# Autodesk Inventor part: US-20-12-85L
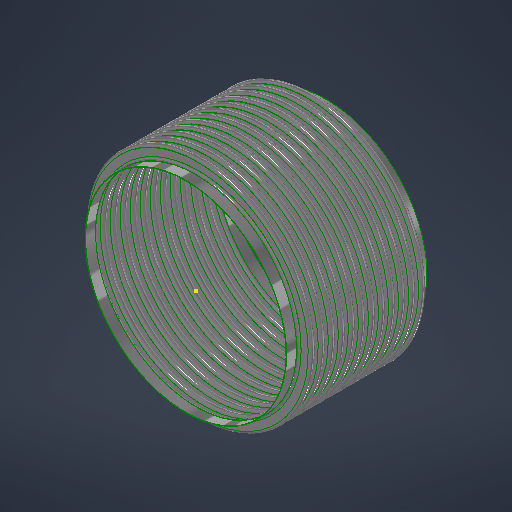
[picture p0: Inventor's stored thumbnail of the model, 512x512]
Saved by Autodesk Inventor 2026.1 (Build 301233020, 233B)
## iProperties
Category: 18 GA (0.048 THICK)
RuleStatus: InUse
Created: 2026-07
Part Number: US-20-12-85L
Project: =STOCK BELLOWS: <Stock Number><SFILL>
Material: ASTM A240-304
Description: =STOCK BELLOWS: <Stock Number>, <SID_> I.D., <SOD_> O.D., <SPLY_> PLY, <Category>, <SNET_CONS> CONS.<PITCH_><STANGENT_> TANGENT<SFILL>
Document SubType Name: Sheet Metal
Designer: LC
Stock Number: U.S-20-12-85L
Surface Area: 659.127 cm^2
Volume: 56.61 cm^3
Sheet Metal Rule: Default
Appearance: STAINLESS STEEL
NET_TUBE: 3.428
COUNTER: 1.500
PBAR: 1.214
PSET: 5.356
PLY: 2
CONS: 2
THK: 0.036
ID: 4.500
OD: 5.500
CONS_: 2
TANGENT: 0.500
PITCH: 0.375
BELLOWS_UPSET: 0.000
NET_CONS: 2
S_CONS: 0
Description_Units: 0
ID_M: 114.30 mm
OD_M: 139.70 mm
THK_M: 0.91 mm
ID_U: 4.500 in
OD_U: 5.500 in
THK_U: 0.036 in
TANGENT2: 0.500
d79: 1.000
d82: 1.000
d83: 26.000
d84: 24.000
d80: 2.571
d81: 10
SID: 2.375
SCONS_: 12
SPITCH: 0.250
SBELLOWS_UPSET: 0.000
SNET_CONS: 12
SS_CONS: 0
SCONS: 8
d174: 8
d177: 0.018
d178: 2.375
d179: 3.000
d180: 0.375
d181: 1.000
d182: 0.000
d190: 8
d191: 1
d192: 1
d193: 8
d194: 0
PART_NUMBER: U.S-20-12-85L
PRESSURE: 85
SIZE: 20.00
STANGENT_: 1.000
d214: 8
d217: 0.030
d218: 6.625
d219: 8.125
d220: 0.500
d221: 1.000
d222: 0.000
d230: 8
d231: 1
d232: 1
d233: 8
d234: 0
STANGENT: 4.000
SPLY_: 1
STHK_: 0.048
SID_: 20.000
SOD_: 22.500
SPITCH_: 1.000
STANGENT__: 1.000
SBELLOWS_UPSET_: 0.000
SDIFF_TAN: 1.000
TAN_TO_TAN: 0.750 in
d252: 2
d275: 2
d287: 0.050
d289: 0.500
d290: 0.000
d263: 2
d265: 1
d268: 2
d269: 0
d286: 2
d288: 1
d291: 2
d292: 0
SOD_NECK: 20 1/8
CFILL: .
SFILL: .
PITCH_: =, <SPITCH_> PITCH,
SREROLL: 0.750
MATTABLE: 20 GA (0.036 THICK)
MESH: ,
CSECT: 2
Author: LC
Keywords: 20 GA (0.036 THICK)
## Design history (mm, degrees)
sketch "Sketch2"
  geometry: L1 (0, -183.595)-(0, 600.956) reference; L2 (58.979, 0)-(57.15, 0); L3 (60.446, -1.467)-(66.554, -1.467); L4 (60.446, -3.296)-(66.554, -3.296); L5 (66.554, -8.058)-(60.446, -8.058); L6 (66.554, -6.229)-(60.446, -6.229); L7 (58.979, -9.525)-(57.15, -9.525); L8 (60.446, 0)-(60.446, -9.525); L9 (66.554, -4.762)-(69.85, -4.763); L10 (57.15, 0)-(57.15, -9.525); L11 (20.376, 102.841)-(20.376, 101.926); L12 (58.262, 488.877)-(58.262, 349.177); L13 (58.262, 479.352)-(58.262, 339.652); L14 (93.133, -58.817)-(93.133, -71.517); L15 (118.746, -66.401)-(118.746, -66.401); L16 (66.554, -6.229)-(66.554, -8.058); L17 (60.446, -6.229)-(60.446, -8.058); L18 (60.446, -7.144)-(66.554, -7.144); L19 (69.85, 0)-(69.85, -9.525); L20 (-66.554, -6.229)-(-66.554, -8.058); L21 (-66.554, -1.467)-(-60.446, -1.467); L22 (-66.554, -3.296)-(-60.446, -3.296); L23 (-60.446, -6.229)-(-66.554, -6.229); L24 (-66.554, -7.144)-(-60.446, -7.144); L25 (-60.446, -8.058)-(-66.554, -8.058); L26 (-60.446, -6.229)-(-60.446, -8.058); L27 (-57.15, -2.522)-(-57.15, -12.047); L28 (-60.446, -4.763)-(-57.15, -4.763); L29 (-66.554, 3.828)-(-66.554, -9.525); L30 (-68.021, 0)-(-69.85, 0); L31 (-69.85, 0)-(-69.85, -9.525); L32 (-68.021, -9.525)-(-69.85, -9.525); A1 r 1.467 centre (60.446, 0) between (58.979, 0) and (60.446, -1.467); A2 r 3.296 centre (60.446, 0) between (57.15, 0) and (60.446, -3.296); A3 r 3.296 centre (66.554, -4.762) between (66.554, -8.058) and (66.554, -1.467); A4 r 1.467 centre (66.554, -4.762) between (66.554, -6.229) and (66.554, -3.296); A5 r 1.467 centre (60.446, -9.525) between (60.446, -8.058) and (58.979, -9.525); A6 r 3.296 centre (60.446, -9.525) between (60.446, -6.229) and (57.15, -9.525); A7 r 2.381 centre (66.554, -4.762) between (66.554, -7.144) and (68.936, -4.762); A8 r 2.381 centre (60.446, -9.525) between (60.446, -7.144) and (58.064, -9.525); A9 r 1.467 centre (-66.554, -9.525) between (-66.554, -8.058) and (-68.021, -9.525); A10 r 1.467 centre (-60.446, -4.763) between (-60.446, -6.229) and (-60.446, -3.296); A11 r 2.381 centre (-60.446, -4.763) between (-60.446, -7.144) and (-58.064, -4.763); A12 r 3.296 centre (-60.446, -4.763) between (-60.446, -8.058) and (-60.446, -1.467); A13 r 2.381 centre (-66.554, -9.525) between (-66.554, -7.144) and (-68.936, -9.525); A14 r 3.296 centre (-66.554, -9.525) between (-66.554, -6.229) and (-69.85, -9.525); A15 r 1.467 centre (-66.554, 0) between (-68.021, 0) and (-66.554, -1.467); A16 r 3.296 centre (-66.554, 0) between (-69.85, 0) and (-66.554, -3.296); 10 further points
  constraints: 62 end point, 38 point on circle, 20 tangent, 16 centre point, 12 parallel, 9 midpoint, 7 vertical, 6 coincident, 6 concentric, 6 point on line, 4 equal radius, 4 perpendicular, 3 horizontal, 1 collinear, 1 horizontal alignment, 10 other
  dimensions: "THK" = 0.9144 distance of L11.start L11.end; "ID" = 114.3 distance of L11.end point (20.376, -12.374); "OD" = 139.7 distance of L12.start L12.end; "PITCH" = 9.525 distance of L12.start L13.start; "TANGENT" = 12.7 distance of L14.start L14.end; "BELLOWS_UPSET" = 0 distance of L15.start L15.end; "d43" = 114.3 diameter of L10 L1 (= ID); "d44" = 139.7 diameter of L9.end L1 (= OD); "d45" = 1.8288 distance between parallel lines of L5 L6 (computed from THK, PLY); "d46" = 3.29565 radius of A3 (computed from PITCH, THK, PLY); "UPSET_PITCH" = 9.525 distance of L2.end L7.end (derived); "SIDEWALL_ANGLE" = 0 deg angle of L3 L9 (derived); "CON_GAP" = 2.9337 distance of point (60.446, -6.229) point (60.446, -3.296) (derived); "TAN1" = 3.74046 dimension on A8 (derived); "TAN2" = 3.74046 dimension on A7 (derived); "LEG1" = 6.1087 distance of L18.start L18.end (derived); "d278" = 1.8288 distance between parallel lines of L25 L23 (derived); "d279" = 3.29565 radius of A12 (derived); "d280" = 9.525 distance of L30.end L31.end (derived); "d281" = 360 deg dimension on L21 L28 (derived); "d282" = 2.9337 distance of point (-66.554, -6.229) point (-66.554, -3.296) (derived); "d283" = 3.74046 dimension on A13 (derived); "d284" = 3.74046 dimension on A11 (derived); "d285" = 6.1087 distance of L24.start L24.end (derived); "d293" = 114.3 diameter of L27 L1 (derived); "d294" = 139.7 diameter of L31 L1 (derived)
  node "Sketch Rectangular Pattern1" dims "d31" = 25.4, "ID" = 114.3
  node "Sketch Rectangular Pattern2" dims "d39" = 25.4, "PITCH" = 9.525
revolve "CONS" stored, may be unused: angle "d48" = 90 deg
node "BELLOW MIDPLANE"
pattern_linear "Rectangular Pattern2" dims "d52" = 9.525 (= UPSET_PITCH)
sketch "Sketch5"
  geometry: C1 r 58.979 at (0, 0) reference; C2 r 57.15 at (0, 0) reference
extrude "TANGENT" new body sketch "Sketch5" distance "d53" = 12.7 (= TANGENT); taper "d54" = 0 deg
revolve "SAMETAN" stored, may be unused: angle "d65" = 90 deg
revolve "DIFFTAN" stored, may be unused: angle "d70" = 90 deg
sketch "Sketch9"
  geometry: L1 (58.391, 0)-(-58.391, 0) reference; L2 (0, -17.78)-(0, 17.78) reference; L3 (41.708, 0)-(-41.708, 0); L4 (41.708, -11.906)-(41.708, 11.906); L5 (29.008, -11.906)-(29.008, 11.906); L6 (15.418, 11.906)-(15.418, -11.906); L7 (-29.008, -11.906)-(-29.008, 11.906); L8 (-41.708, -11.906)-(-41.708, 11.906); L9 (40.914, -11.906)-(40.914, 11.906); L10 (41.708, -11.906)-(40.914, -11.906); L11 (41.708, 11.906)-(40.914, 11.906); L12 (15.815, 11.906)-(15.022, 11.906); L13 (15.022, 11.906)-(15.022, -11.906); L14 (15.022, -11.906)-(15.815, -11.906); L15 (15.815, -11.906)-(15.815, 11.906); L16 (-15.815, 11.906)-(-15.815, -11.906); L17 (-15.418, 11.906)-(-15.418, -11.906); L18 (-15.815, -11.906)-(-15.022, -11.906); L19 (-15.022, -11.906)-(-15.022, 11.906); L20 (-15.022, 11.906)-(-15.815, 11.906); L21 (-41.708, -11.906)-(-40.914, -11.906); L22 (-40.914, -11.906)-(-40.914, 11.906); L23 (-40.914, 11.906)-(-41.708, 11.906); L24 (-41.708, 11.906)-(-41.708, -11.906); L25 (41.708, -0.397)-(-41.708, -0.397); L26 (-41.708, -0.397)-(-41.708, 0.397); L27 (-41.708, 0.397)-(41.708, 0.397); L28 (41.708, 0.397)-(41.708, -0.397); L29 (-41.708, 11.906)-(41.708, 11.906); L30 (41.708, 11.906)-(41.708, 12.7); L31 (41.708, 12.7)-(-41.708, 12.7); L32 (-41.708, 12.7)-(-41.708, 11.906); L33 (41.708, -11.906)-(-41.708, -11.906); L34 (-41.708, -11.906)-(-41.708, -12.7); L35 (-41.708, -12.7)-(41.708, -12.7); L36 (41.708, -12.7)-(41.708, -11.906); 30 further points
  constraints: 68 end point, 13 midpoint, 13 parallel, 8 horizontal, 7 perpendicular, 6 equal length, 3 point on line, 2 vertical, 14 other
  dimensions: "d115" = 23.8125 distance of L4.start L4.end (derived); "d116" = 12.7 distance between parallel lines of L4 L5 (derived); "d117" = 13.58962 distance between parallel lines of L5 L6 (derived); "d125" = 44.42645 distance between parallel lines of L7 L6 (derived); "d127" = 12.7 distance between parallel lines of L8 L7 (derived); "d128" = 26.28962 distance between parallel lines of L6 L4 (derived); "d130" = 83.41607 distance between parallel lines of L8 L4 (derived); "RULER_THK" = 0.79375 distance between parallel lines of L4 L9; "d135" = 0.79375 distance of L13.end L14.end (derived); "d138" = 30.83684 distance of L13.end L16.end (derived); "d143" = 0.79375 distance of L22.end L8.end (derived); "d144" = 0.79375 distance between parallel lines of L27 L25 (derived)
extrude "RULER" join sketch "Sketch9" distance "d149" = 0.79375 (derived); taper "d150" = 0 deg
extrude "BARS" join sketch "Sketch9" distance "d151" = 0.79375 (derived); taper "d152" = 0 deg
pattern_linear "Rectangular Pattern4" dims "d155" = 30.83684 (derived)
sketch "Sketch13"
  geometry: L1 (93.149, -52.467)-(93.149, -77.867); L2 (255.219, 0)-(254, 0); L3 (255.219, -25.4)-(254, -25.4); L4 (278.79, -19.66)-(260.96, -19.66); L5 (278.79, -18.44)-(260.96, -18.44); L6 (278.79, -12.7)-(285.75, -12.7); L7 (260.96, -5.74)-(278.79, -5.74); L8 (260.96, 0)-(260.96, -25.4); L9 (254, 0)-(254, -25.4); L10 (58.254, -203.273)-(58.254, -774.773); L11 (58.254, -228.673)-(58.254, -800.173); L12 (58.254, -279.473)-(58.254, -850.973); L13 (58.254, -304.873)-(58.254, -876.373); L14 (58.254, -330.273)-(58.254, -901.773); L15 (58.254, -355.673)-(58.254, -927.173); L16 (58.254, -381.073)-(58.254, -952.573); L17 (58.254, -254.073)-(58.254, -825.573); L18 (20.376, 103.145)-(20.376, 101.926); L19 (260.96, -6.96)-(278.79, -6.96); L20 (0, -1123.076)-(0, 307.516) reference; L21 (-52.07, 0)-(312.42, 0) reference; A1 r 5.74 centre (260.96, 0) between (255.219, 0) and (260.96, -5.74); A2 r 5.74 centre (260.96, -25.4) between (260.96, -19.66) and (255.219, -25.4); A3 r 6.96 centre (260.96, -25.4) between (260.96, -18.44) and (254, -25.4); A4 r 5.74 centre (278.79, -12.7) between (278.79, -18.44) and (278.79, -6.96); A5 r 6.96 centre (278.79, -12.7) between (278.79, -19.66) and (278.79, -5.74); A6 r 6.96 centre (260.96, 0) between (254, 0) and (260.96, -6.96); 6 further points; 1 other entity
  constraints: 38 end point, 15 point on circle, 9 tangent, 6 centre point, 6 parallel, 5 vertical alignment, 4 point on line, 4 vertical, 3 coincident, 3 concentric, 2 collinear, 2 equal radius, 1 horizontal, 1 perpendicular, 23 other
  dimensions: "SBELLOWS_UPSET_" = 0 distance of point (118.762, -66.401) point (118.762, -66.401); "STOTAL_THK_BELLOW__" = 1.2192 distance between parallel lines of L4 L5 (derived); "d224" = 6.9596 radius of A5 (derived); "d225" = 25.4 distance of L2.end L3.end (derived); "SSIDEWALL_ANGLE_" = 0 deg angle of L7 L6 (derived); "SSCON_GAP_" = 11.4808 distance of point (260.96, -18.44) point (260.96, -6.96) (derived); "d235" = 508 diameter of L9 L20 (derived); "d236" = 571.5 diameter of L6.end L20 (derived)
  node "Sketch Rectangular Pattern4" dims "d228" = 25.4
  node "Sketch Rectangular Pattern5" dims "d229" = 25.4
revolve "SBELLOW" stored, may be unused: angle "d197" = 90 deg
pattern_linear "Rectangular Pattern5" dims "d204" = 25.4 (derived)
revolve "STANGENT" stored, may be unused: angle "d240" = 90 deg
revolve "SSAMETAN" stored, may be unused: angle "d241" = 90 deg
revolve "SDIFFTAN" stored, may be unused: angle "d246" = 90 deg
revolve "INVCON" stored, may be unused: angle "d295" = 90 deg
pattern_linear "Rectangular Pattern6" dims "d298" = 9.525 (derived)
revolve "INVTANGENT" stored, may be unused: angle "d302" = 90 deg
revolve "INVSAMETAN" stored, may be unused: angle "d307" = 90 deg
revolve "INVDIFFTAN" stored, may be unused: angle "d312" = 90 deg
sketch "ID BELLOW MOUNT CALC"
  geometry: L1 (44.45, 0)-(38.1, 0); L2 (38.1, 0)-(38.1, 12.7); L3 (38.1, 12.7)-(44.45, 12.7); L4 (44.45, 12.7)-(44.45, 0); L5 (36.513, 12.7)-(34.684, 12.7); L6 (34.684, 12.7)-(34.684, 0); L7 (34.684, 0)-(36.513, 0); L8 (36.513, 0)-(36.513, 12.7); L9 (0, -2.54)-(0, 15.24) reference; L10 (-8.89, 0)-(53.34, 0) reference; 1 further point
  constraints: 16 end point, 5 parallel, 2 collinear, 2 horizontal, 2 perpendicular
  dimensions: "d314" = 12.7 distance of L5.end L6.end (derived); "d315" = 1.8288 distance of L5.start L5.end (derived); "IG" = 1.5875 distance between parallel lines of L2 L8; "PIPE_OD" = 88.9 diameter of L4 L9; "PIPE_WALL" = 6.35 distance of L2.end L3.end; "ID_MT_BELLOW" = 69.3674 diameter of L6 L9 (derived)
revolve "CFILL" stored, may be unused: angle "d320" = 90 deg
pattern_linear "Rectangular Pattern7" dims "d323" = 9.525 (derived)
revolve "SFILL" stored, may be unused: angle "d324" = 90 deg
pattern_linear "Rectangular Pattern8" dims "d327" = 25.4 (derived)
node "STOCK BELLOW MIDPLANE"
sketch "Sketch21"
  geometry: L1 (0, -100.013)-(0, 100.013) reference; L2 (-100.013, 0)-(100.013, 0) reference; L3 (-0.099, 71.437)-(0.099, 71.437); L4 (0.099, 71.437)-(0.099, 55.562); L5 (0.099, 55.562)-(-0.099, 55.562); L6 (-0.099, 55.562)-(-0.099, 71.437); C1 r 55.562 at (0, 0); C2 r 71.437 at (0, 0); 3 further points
  constraints: 8 end point, 2 centre point, 2 coincident, 2 parallel, 2 tangent, 1 horizontal, 1 perpendicular, 1 other
  dimensions: "d329" = 111.125 diameter of C1 (derived); "d330" = 142.875 diameter of C2 (derived); "d331" = 0.19844 distance of L3.start L3.end
extrude "CLAMSHELL" cut sketch "Sketch21" extent not by distance; stored distance "d332" = 0; taper "d333" = 0 deg
pattern_circular "Circular Pattern1" dims angle "d335" = 180 deg (derived)
node "BELLOW"
sketch "Sketch6"
  geometry: L1 (-19.05, 58.979)-(-6.35, 58.979); L2 (-6.35, 58.979)-(-6.35, 57.15); L3 (-6.35, 57.15)-(-19.05, 57.15); L4 (-19.05, 57.15)-(-19.05, 58.979); L5 (2.54, 0)-(-59.69, 0) reference; L6 (-38.1, -108.388)-(-38.1, 156.601) reference; 1 further point
  constraints: 8 end point, 2 parallel, 1 horizontal, 1 perpendicular
  dimensions: "d61" = 12.7 distance of L2.end L3.end (derived); "d62" = 1.8288 distance of L1.end L2.end (derived); "d63" = 114.3 diameter of L3 L5 (derived); "d64" = 19.05 distance between parallel lines of L4 L6 (derived)
sketch "Sketch12"
  geometry: 1 further point
sketch "Sketch14"
  geometry: L1 (-25.4, 255.219)-(0, 255.219); L2 (0, 255.219)-(0, 254); L3 (0, 254)-(-25.4, 254); L4 (-25.4, 254)-(-25.4, 255.219); L5 (5.08, 0)-(-30.48, 0) reference; L6 (0, -45.964)-(0, 275.783) reference; 1 further point
  constraints: 8 end point, 2 parallel, 1 collinear, 1 horizontal, 1 perpendicular
  dimensions: "d237" = 1.2192 distance of L3.end L1.start (derived); "d238" = 508 diameter of L3 L5 (derived); "d239" = 25.4 distance of L1.start L1.end (derived); "SOD_NECK" = 510.4384 diameter of L1 L5 (derived)
sketch "Sketch15"
  geometry: L1 (-45.964, 0)-(275.783, 0) reference; L2 (254, -304.8)-(255.219, -304.8); L3 (255.219, -304.8)-(255.219, -330.2); L4 (255.219, -330.2)-(254, -330.2); L5 (254, -330.2)-(254, -304.8); L6 (0, -398.78)-(0, 81.28) reference; 1 further point
  constraints: 8 end point, 2 parallel, 1 horizontal, 1 perpendicular
  dimensions: "d205" = 25.4 distance of L4.end L2.start (derived); "d206" = 1.2192 distance of L3.end L4.end (derived); "d207" = 508 diameter of L5 L6 (derived); "d208" = 304.8 distance between parallel lines of L1 L2 (derived)
node "TANGENT_"
node "SAME_TAN"
sketch "Sketch8"
  geometry: L1 (58.979, -19.05)-(57.15, -19.05); L2 (57.15, -19.05)-(57.15, -31.75); L3 (57.15, -31.75)-(58.979, -31.75); L4 (58.979, -31.75)-(58.979, -19.05); L5 (0, -40.64)-(0, 21.59) reference; L6 (-108.388, 0)-(156.601, 0) reference; 1 further point
  constraints: 8 end point, 2 parallel, 1 horizontal, 1 perpendicular
  dimensions: "d66" = 114.3 diameter of L2 L5 (derived); "TOTAL_THK_BELLOW" = 1.8288 distance of L2.end L3.end (derived); "d68" = 19.05 distance between parallel lines of L1 L6 (derived); "d69" = 12.7 distance of L1.end L2.end (derived)
node "DIFF_TAN"
node "Sketch Rectangular Pattern3" dims "d138" = 30.83684 (derived), "d141" = 25.4
node "SBELLOW_"
node "STANGENT_"
node "SSAME_TAN"
sketch "Sketch16"
  geometry: L1 (255.219, -304.8)-(254, -304.8); L2 (254, -304.8)-(254, -330.2); L3 (254, -330.2)-(255.219, -330.2); L4 (255.219, -330.2)-(255.219, -304.8); L5 (0, -398.78)-(0, 81.28) reference; L6 (-45.964, 0)-(275.783, 0) reference; 1 further point
  constraints: 8 end point, 2 parallel, 1 horizontal, 1 perpendicular
  dimensions: "SDIFF_TAN" = 25.4 distance of L3.end L1.start; "d243" = 1.2192 distance of L2.end L3.end (derived); "d244" = 304.8 distance between parallel lines of L1 L6 (derived); "d245" = 508 diameter of L2 L5 (derived)
node "SDIFF_TAN"
body "Solid15"
sketch "Sketch17"
  geometry: L1 (69.85, 12.7)-(68.021, 12.7); L2 (68.021, 12.7)-(68.021, 0); L3 (68.021, 0)-(69.85, 0); L4 (69.85, 0)-(69.85, 12.7); L5 (0, -2.54)-(0, 15.24) reference; L6 (-13.97, 0)-(83.82, 0) reference; 2 further points
  constraints: 8 end point, 2 parallel, 1 horizontal, 1 midpoint, 1 perpendicular, 1 point on line
  dimensions: "INVTANGENT" = 12.7 distance of L3.end L1.start (derived); "d300" = 1.8288 distance of L1.start L1.end (derived); "d301" = 139.7 diameter of L4 L5 (derived)
body "Solid16"
sketch "Sketch18"
  geometry: L1 (69.85, -19.05)-(68.021, -19.05); L2 (68.021, -19.05)-(68.021, -31.75); L3 (68.021, -31.75)-(69.85, -31.75); L4 (69.85, -31.75)-(69.85, -19.05); L5 (-13.97, 0)-(83.82, 0) reference; L6 (0, -40.64)-(0, 21.59) reference; 1 further point
  constraints: 8 end point, 2 parallel, 1 horizontal, 1 perpendicular
  dimensions: "d303" = 19.05 distance between parallel lines of L1 L5 (derived); "d304" = 12.7 distance of L3.end L1.start (derived); "d305" = 1.8288 distance of L2.end L3.end (derived); "d306" = 139.7 diameter of L4 L6 (derived)
body "Solid17"
sketch "Sketch19"
  geometry: L1 (69.85, -19.05)-(68.021, -19.05); L2 (68.021, -19.05)-(68.021, -31.75); L3 (68.021, -31.75)-(69.85, -31.75); L4 (69.85, -31.75)-(69.85, -19.05); L5 (0, -40.64)-(0, 21.59) reference; L6 (-13.97, 0)-(83.82, 0) reference; 1 further point
  constraints: 8 end point, 2 parallel, 1 horizontal, 1 perpendicular
  dimensions: "d308" = 12.7 distance of L1.end L2.end (derived); "d309" = 139.7 diameter of L4 L5 (derived); "d310" = 1.8288 distance of L2.end L3.end (derived); "d311" = 19.05 distance between parallel lines of L1 L6 (derived)
body "Solid18"
body "Solid19"
body "Solid20"
other parameters: "BMPL" = -152.4, "PSET" = 136.0424 (computed from OD, THK, PLY) [user parameter], "PBAR" = 30.83684 (= 0.570796 x PITCH + OD - ID) [user parameter; used in 1 equation term], "COUNTER" = 15 [user parameter], "NET_TUBE" = 87.07367 (computed from CONS_, PBAR, TANGENT) [user parameter], "S_CONS" = 0 [user parameter; used in 1 equation term], "ID_M" = 114.3 (= ID) [user parameter], "OD_M" = 139.7 (= OD) [user parameter], "THK_M" = 0.9144 (= THK) [user parameter], "ID_U" = 114.3 (= ID) [user parameter], "OD_U" = 139.7 (= OD) [user parameter], "THK_U" = 0.9144 (= THK) [user parameter], "D_UNITS" = 0 [user parameter], "TANGENT2" = 12.7 [user parameter], "TAN_TO_TAN" = 19.05 [user parameter], "OD_NECK" = 117.9576 [user parameter], "d79" = 25.4, "d80" = 65.29823 [user parameter], "d82" = 25.4, "d83" = 660.4, "d84" = 609.6, "sa_0" = 4, "FRAME_THK" = 0.79375 [user parameter], "CON_FLAT" = 13.58962 [user parameter], "SID" = 60.325 [user parameter], "SPITCH" = 6.35 [user parameter], "STANGENT_" = 25.4 [user parameter], "SBELLOWS_UPSET" = 0 [user parameter], "SS_CONS" = 0 [user parameter], "STAN_TO_TAN_" = 304.8 [user parameter], "d100" = 1.2192 [user parameter], "d191" = 25.4 [user parameter], "d194" = 0 [user parameter], "STANGENT" = 101.6 [user parameter], "d234" = 0 [user parameter], "SUPSET_PITCH_" = 25.4 [user parameter], "d269" = 0 [user parameter], "d287" = 1.27, "d289" = 12.7, "d290" = 0, "d292" = 0 [user parameter], "Thickness" = 3.048 (derived), "KFactor" = 4.4, "BendRadius" = 3.048 (derived), "BendReliefWidth" = 3.048 (derived), "BendReliefDepth" = 1.524 (derived), "CornerReliefSize" = 12.192 (derived), "SeamGap" = 0.00508, "MinimumRemnant" = 6.096 (derived), "TransitionRadius" = 3.048 (derived), "JacobiRadiusSize" = 3.048 (derived), "GapSize" = 3.048 (derived), "SREROLL" = 19.05 [user parameter], "CUR_STK_PITCH" = 25.4 [user parameter], "d328" = -152.4 (derived), "CSECTDEG" = 180 deg [user parameter]
